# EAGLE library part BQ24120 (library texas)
SINGLE-CHIP SWITCHMODE, LI-ION AND LI-POLYMER CHARGE-MANAGEMENT IC WITH ENHANCED EMI PERFORMANCE(bqSWITCHER) Source: www.ti.com .. TI-bq24125.pdf
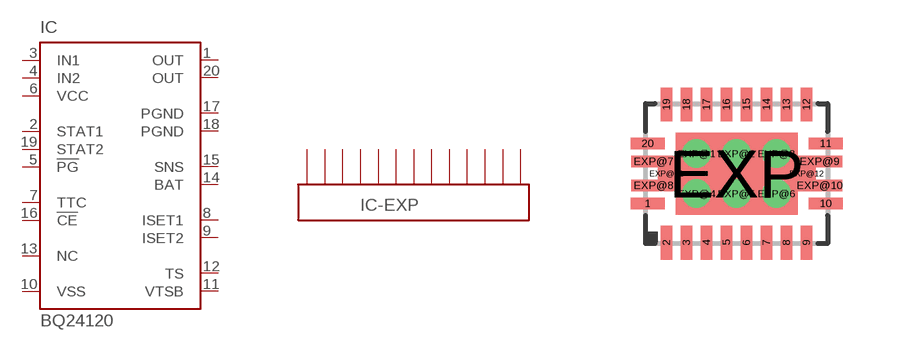
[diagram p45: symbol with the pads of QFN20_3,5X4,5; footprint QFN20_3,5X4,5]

Designator prefix IC; gates G$1=BQ24120-1 -EXP=EXP

## BQ24120 (MPN: BQ24120RHLTG4; OC_FARNELL: 1230453; OC_NEWARK: 12M9386)  [QFN20_3,5X4,5]
1  G$1:OUT  out
2  G$1:STAT1  out
3  G$1:IN1  in
4  G$1:IN2  in
5  G$1:!PG  out
6  G$1:VCC  in
7  G$1:TTC  pas
8  G$1:ISET1
9  G$1:ISET2
10  G$1:VSS  pwr
11  G$1:VTSB  out
12  G$1:TS  in
13  G$1:NC  nc
14  G$1:BAT  in
15  G$1:SNS  in
16  G$1:!CE  in
17  G$1:PGND  in
18  G$1:PGND  in
19  G$1:STAT2  out
20  G$1:OUT  in
EXP  -EXP:7  in
EXP@1  -EXP:1  in
EXP@2  -EXP:2  in
EXP@3  -EXP:3  in
EXP@4  -EXP:4  in
EXP@5  -EXP:5  in
EXP@6  -EXP:6  in
EXP@7  -EXP:8  in
EXP@8  -EXP:9  in
EXP@9  -EXP:10  in
EXP@10  -EXP:11  in
EXP@11  -EXP:12  in
EXP@12  -EXP:13  in

## Footprint QFN20_3,5X4,5 (pad centres in mm)
RHL (R-PQFP-N20) Set in DRC - Same Signals - SMD to SMD and SMD to PAD = 0. Source: www.ti.com .. TI-bq24125.pdf
smd 0.85 x 0.28: 1 -2.225,-0.75; 10 2.225,-0.75; 11 2.225,0.75; 20 -2.225,0.75
smd 0.28 x 0.85: 2 -1.75,-1.725; 3 -1.25,-1.725; 4 -0.75,-1.725; 5 -0.25,-1.725; 6 0.25,-1.725; 7 0.75,-1.725; 8 1.25,-1.725; 9 1.75,-1.725; 12 1.75,1.725; 13 1.25,1.725; 14 0.75,1.725; 15 0.25,1.725; 16 -0.25,1.725; 17 -0.75,1.725; 18 -1.25,1.725; 19 -1.75,1.725
smd 3.05 x 2.05: EXP 0,0
drill 0.2 pad 0.3 round: EXP@1 -1,0.5; EXP@2 0,0.5; EXP@3 1,0.5; EXP@4 -1,-0.5; EXP@5 0,-0.5; EXP@6 1,-0.5
smd 1.125 x 0.28: EXP@7 -2.075,0.3; EXP@8 -2.075,-0.3; EXP@9 2.075,0.3; EXP@10 2.075,-0.3
smd 0.45 x 0.4: EXP@11 -1.75,0; EXP@12 1.75,0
